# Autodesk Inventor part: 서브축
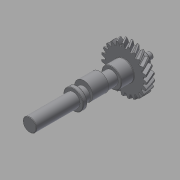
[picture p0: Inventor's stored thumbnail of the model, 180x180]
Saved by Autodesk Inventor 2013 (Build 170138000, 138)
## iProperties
Created: 2016-12
Part Number: 서브축
Material: 강철, 탄소
Document SubType Name: Modeling
Designer: mduedu
Categories: <?xml version="1.0" encoding="UTF-16"?> <MemberInstance><Categories><FamilyTemplate><FamilyTemplateParameter ValueType="xs:double" Id="1" ObjectReferenceKey="da
Density: 7.87 g/cm^3
Mass: 483.64 g
Surface Area: 167.141 cm^2
Volume: 61.4536 cm^3
CustomPartVersion: 1
Author: mduedu
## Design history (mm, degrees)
sketch "Sketch1"
  geometry: C1 r 28.558 at (0, 0)
  constraints: 1 centre point
  dimensions: "d0" = 57.11622 diameter of C1 (= da_da)
extrude "Extrusion1" new body sketch "Sketch1" distance "d1" = 10 (= da_b); taper "d2" = 0 deg
workplane "Work Plane2"
sketch "Sketch2"
  geometry: C1 r 28.558 at (0, 0) reference; C2 r 26.558 at (0, 0)
  constraints: 1 centre point, 1 coincident
  dimensions: "d3" = 53.11622 diameter of C2 (= da_dw)
feature "피치 지름" sketch "Sketch2" dims "d4" = 10, "d5" = 0
workplane "Work Plane8"
workplane "Work Plane9"
feature "스퍼 기어" dims "da_b" = 10, "da_d" = 53.11622, "da_aw" = 43.87862, "da_da" = 57.11622, "da_df" = 48.11622, "da_dw" = 53.11622, angle "da_beta" = 30 deg, "da_lefttooth" = 10, "da_righttooth" = 0
sketch "스케치3"
  geometry: C1 r 12.5 at (0, 0); 1 further point
  constraints: 1 centre point, 1 coincident
  dimensions: "d49" = 25 diameter of C1
extrude "돌출2" join sketch "스케치3" distance "d50" = 16; taper "d51" = 0 deg
sketch "스케치4"
  geometry: C1 r 8.5 at (0, 0); 1 further point
  constraints: 1 centre point, 1 coincident
  dimensions: "d52" = 17 diameter of C1
extrude "돌출3" join sketch "스케치4" distance "d53" = 103; taper "d54" = 0 deg
sketch "스케치5"
  geometry: C1 r 7.5 at (0, 0); 1 further point
  constraints: 1 centre point, 1 coincident
  dimensions: "d55" = 15 diameter of C1
extrude "돌출4" join sketch "스케치5" distance "d56" = 16; taper "d57" = 0 deg
sketch "스케치6"
  geometry: C1 r 4 at (0, 0); 1 further point
  constraints: 1 centre point, 1 coincident
  dimensions: "d58" = 8 diameter of C1
extrude "돌출5" join sketch "스케치6" distance "d59" = 7; taper "d60" = 0 deg
chamfer "모따기1" distance "d61" = 0.5; stored, may be unused: second distance "d62" = 2, angle "d63" = 45 deg
fillet "모깎기1" dims "d64" = 0.5
node "작업 평면11"
sketch "스케치7"
  geometry: C1 r 11.5 at (0, 3); C2 r 8.5 at (0, 0) reference; 1 further point
  constraints: 1 centre point, 1 tangent, 1 vertical alignment
  dimensions: "d66" = 3 distance of point (0, 0) C1.centre; "d67" = 23 diameter of C1 (derived)
extrude "돌출6" join sketch "스케치7" stored distance "d68" = 20; taper "d69" = 0 deg
node "작업 평면12"
sketch "스케치8"
  geometry: C1 r 12.5 at (0, 0) reference; 1 further point
extrude "돌출7" join sketch "스케치8" distance "d71" = 5; taper "d72" = 0 deg
chamfer "모따기2" distance "d73" = 0.5; stored, may be unused: second distance "d74" = 2, angle "d75" = 45 deg
body "Solid1"
body "Srf1"
other parameters: "d16" = 43.87862 (= da_aw), "d17" = 0, "d34" = 1.36591 (computed from da_z), "d39" = 0, "d41" = 0, "d43" = 43.87862 (= da_aw), "d46" = 43.87862 (= da_aw), "d47" = 0, "d48" = 0, "d65" = 25, "d70" = 48
